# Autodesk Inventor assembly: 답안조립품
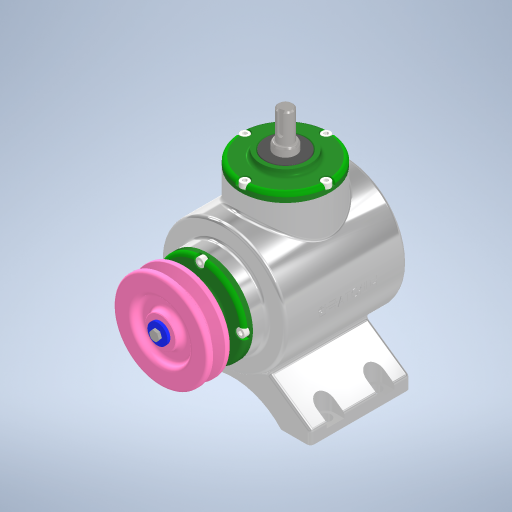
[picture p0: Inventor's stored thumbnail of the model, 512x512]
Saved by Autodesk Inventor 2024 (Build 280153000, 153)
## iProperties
Created: 2023-08
Part Number: 답안조립품
Document SubType Name: Assembly
Designer: Owner
Author: Owner
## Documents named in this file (17)
- C:\Users\Owner\Desktop\730813V1009\답안조립품.iam
- C:\Users\Owner\Desktop\730813V1009\본체.ipt
- C:\Users\Owner\Desktop\730813V1009\V-벨트풀리.ipt
- C:\Users\Owner\Desktop\730813V1009\메인 베벨기어.ipt
- C:\Users\Owner\Desktop\730813V1009\메인 축.ipt
- 메인 축.ipt
- C:\Users\Owner\Desktop\730813V1009\베어링 6203.ipt
- C:\Users\Owner\Desktop\730813V1009\볼트 M4 x 10.ipt
- C:\Users\Owner\Desktop\730813V1009\서브 베벨기어.ipt
- C:\Users\Owner\Desktop\730813V1009\서브 축.ipt
- 서브 축.ipt
- C:\Users\Owner\Desktop\730813V1009\오일실 17 x 32 x 8.ipt
- C:\Users\Owner\Desktop\730813V1009\와셔 4 x 16.ipt
- C:\Users\Owner\Desktop\730813V1009\육각볼트 M4 x 8.ipt
- C:\Users\Owner\Desktop\730813V1009\커버.ipt
- C:\Users\Owner\Desktop\730813V1009\키 4 x 4 x 14.ipt
- C:\Users\Owner\Desktop\730813V1009\키 5 x 5 x 14.ipt
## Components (1 placed, 1 different names)
1. V-벨트풀리:1
